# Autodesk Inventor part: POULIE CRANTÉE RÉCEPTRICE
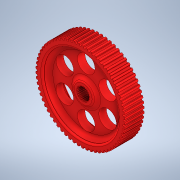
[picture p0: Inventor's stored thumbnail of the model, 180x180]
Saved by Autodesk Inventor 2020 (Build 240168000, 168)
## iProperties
Created: 2003-05
Part Number: POULIE CRANTÉE RÉCEPTRICE
Material: Générique
Document SubType Name: Modeling
Designer: Bruno
Density: 1 g/cm^3
Appearance: Par défaut
Author: Bruno
Sending System: SolidWorks 2011
Last Author: Professeur
Last Saved: 2014-11-10
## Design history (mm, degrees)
feature "Répétition circulaire2"
node "Solide1"
